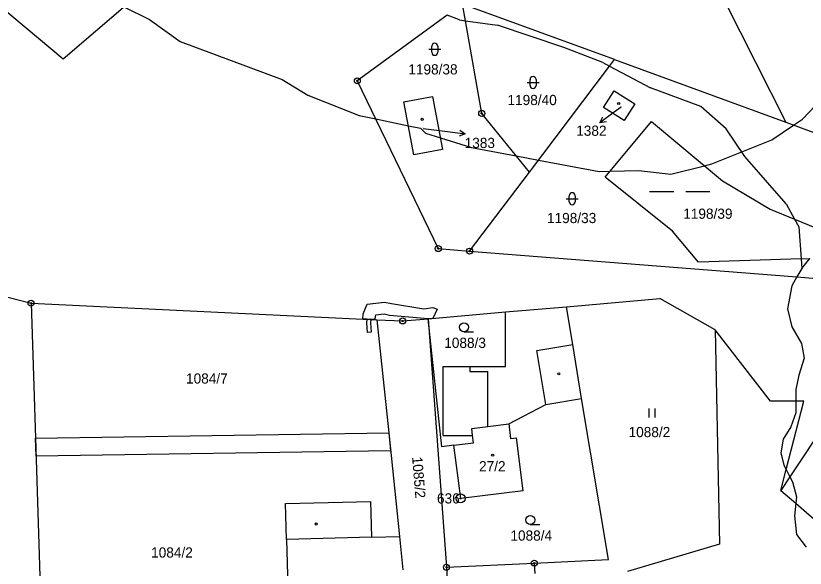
# Model space of a CAD drawing. Extents: x -439246 to -433691, y -1130252 to -1121148.
# Drawn here: x -438464.2 to -438332.6, y -1123574.8 to -1123482.7 of the extents above; entities that cross this region are included whole.
import ezdxf

# ---------------------------------------------------------------- set-up
doc = ezdxf.new("R2010")
doc.units = 0
for name, color, linetype in [('Vrstva 1', 7, 'Continuous'), ('Vrstva 16', 7, 'Continuous'), ('Vrstva 17', 7, 'Continuous'), ('Vrstva 18', 7, 'Continuous'), ('Vrstva 19', 7, 'Continuous'), ('Vrstva 24', 7, 'Continuous'), ('Vrstva 25', 7, 'Continuous'), ('Vrstva 3', 7, 'Continuous'), ('Vrstva 30', 7, 'Continuous'), ('Vrstva 37', 7, 'Continuous'), ('Vrstva 4', 7, 'Continuous'), ('Vrstva 52', 7, 'Continuous')]:
    doc.layers.add(name, color=color, linetype=linetype)

msp = doc.modelspace()

# ---------------------------------------------------------------- linework, layer by layer
at = {"layer": 'Vrstva 1'}
for p, q in [((-438389.25, -1123483.53), (-438389.74, -1123480.75)), ((-438386.53, -1123498.98), (-438389.25, -1123483.53)), ((-438364.37, -1123489.98), (-438335.85, -1123500.47)), ((-438378.59, -1123508.78), (-438365.22, -1123491.11)), ((-438378.59, -1123508.78), (-438386.53, -1123498.98)), ((-438365.96, -1123509.63), (-438358.22, -1123500.32)), ((-438358.22, -1123500.32), (-438346.4, -1123510.22)), ((-438388.55, -1123521.95), (-438378.59, -1123508.78)), ((-438354.73, -1123518.6), (-438365.96, -1123509.63)), ((-438346.4, -1123510.22), (-438338.42, -1123514.97)), ((-438338.42, -1123514.97), (-438334.38, -1123516.62)), ((-438334.38, -1123516.62), (-438328.41, -1123519.06)), ((-438350.41, -1123523.81), (-438354.73, -1123518.6)), ((-438388.55, -1123521.95), (-438333.97, -1123526.25)), ((-438333.3, -1123523.25), (-438350.41, -1123523.81)), ((-438333.3, -1123523.25), (-438331.83, -1123523.2)), ((-438461.66, -1123530.63), (-438460.93, -1123553.15)), ((-438404.01, -1123533.39), (-438402.04, -1123552.25)), ((-438460.93, -1123553.15), (-438402.04, -1123552.25)), ((-438460.93, -1123553.15), (-438459.65, -1123592.69)), ((-438402.04, -1123552.25), (-438400.24, -1123569.55)), ((-438377.77, -1123573.98), (-438377.67, -1123575.68))]:
    msp.add_line(p, q, dxfattribs=at)
for points in [[(-438456.3, -1123489.9), (-438433.99, -1123470.7)], [(-438469.05, -1123479.23), (-438456.3, -1123489.9)], [(-438364.37, -1123489.98), (-438389.74, -1123480.75)], [(-438345.94, -1123480.44), (-438335.85, -1123500.47)], [(-438392.32, -1123482.63), (-438407.27, -1123493.56)], [(-438365.22, -1123491.11), (-438364.37, -1123489.98)], [(-438407.27, -1123493.56), (-438393.78, -1123521.54)], [(-438366.22, -1123498.03), (-438364.47, -1123495.23), (-438361.03, -1123497.41), (-438362.78, -1123500.19), (-438366.22, -1123498.03)], [(-438399.5, -1123497.08), (-438394.73, -1123496.19)], [(-438394.73, -1123496.19), (-438393.05, -1123505.01)], [(-438397.84, -1123505.87), (-438399.5, -1123497.08)], [(-438335.85, -1123500.47), (-438330.11, -1123502.58)], [(-438393.05, -1123505.01), (-438397.84, -1123505.87)], [(-438393.78, -1123521.54), (-438388.55, -1123521.95)], [(-438488.42, -1123523.74), (-438461.66, -1123530.63)], [(-438333.97, -1123526.25), (-438329.34, -1123526.61)], [(-438461.66, -1123530.63), (-438404.01, -1123533.39)], [(-438372.41, -1123531.22), (-438356.83, -1123529.86)], [(-438347.62, -1123535.06), (-438356.83, -1123529.86)], [(-438395.44, -1123533.23), (-438382.54, -1123532.1)], [(-438382.54, -1123532.1), (-438372.41, -1123531.22)], [(-438382.54, -1123541.2), (-438382.54, -1123532.1)], [(-438371.36, -1123537.53), (-438372.41, -1123531.22)], [(-438316.41, -1123531.43), (-438335.17, -1123559.57)], [(-438404.01, -1123533.39), (-438399.71, -1123533.6)], [(-438399.71, -1123533.6), (-438395.44, -1123533.23)], [(-438395.44, -1123533.23), (-438392.41, -1123574.67)], [(-438393.18, -1123554.57), (-438395.44, -1123533.23)], [(-438338.37, -1123546.96), (-438347.62, -1123535.06)], [(-438347.62, -1123535.06), (-438346.87, -1123570.81)], [(-438369.87, -1123546.51), (-438371.36, -1123537.53)], [(-438392.97, -1123552.69), (-438392.97, -1123541.2)], [(-438392.97, -1123541.2), (-438388.52, -1123541.2)], [(-438388.52, -1123541.2), (-438382.54, -1123541.2)], [(-438375.85, -1123547.5), (-438369.87, -1123546.51)], [(-438365.41, -1123573.39), (-438369.87, -1123546.51)], [(-438382.02, -1123550.73), (-438375.85, -1123547.5)], [(-438334.17, -1123546.98), (-438338.37, -1123546.96)], [(-438335.79, -1123558.37), (-438332.85, -1123546.99)], [(-438332.85, -1123546.99), (-438334.17, -1123546.98)], [(-438382.02, -1123550.73), (-438381.71, -1123553.21)], [(-438392.97, -1123552.69), (-438388.05, -1123552.69)], [(-438387.9, -1123553.9), (-438388.05, -1123552.69)], [(-438381.71, -1123553.21), (-438380.72, -1123553.09)], [(-438379.62, -1123561.92), (-438380.72, -1123553.09)], [(-438391.16, -1123554.31), (-438393.18, -1123554.57)], [(-438391.16, -1123554.31), (-438387.9, -1123553.9)], [(-438390.03, -1123563.22), (-438391.16, -1123554.31)], [(-438336.68, -1123561.84), (-438335.79, -1123558.37)], [(-438335.17, -1123559.57), (-438336.68, -1123561.84)], [(-438379.62, -1123561.92), (-438390.03, -1123563.22)], [(-438336.68, -1123561.84), (-438334.18, -1123564)], [(-438419.23, -1123564.05), (-438405.01, -1123563.68)], [(-438404.85, -1123569.67), (-438405.01, -1123563.68)], [(-438419.07, -1123570.05), (-438419.23, -1123564.05)], [(-438334.18, -1123564), (-438321.87, -1123574.68)], [(-438419.07, -1123570.05), (-438418.87, -1123577.86)], [(-438404.85, -1123569.67), (-438400.24, -1123569.55)], [(-438400.24, -1123569.55), (-438399.66, -1123575.12)], [(-438346.87, -1123570.81), (-438362.22, -1123575.37)], [(-438392.41, -1123574.67), (-438377.77, -1123573.98)], [(-438377.77, -1123573.98), (-438365.41, -1123573.39)], [(-438392.41, -1123574.67), (-438391.41, -1123593.5)]]:
    msp.add_lwpolyline(points, dxfattribs=at)
at = {"layer": 'Vrstva 16'}
for p, q in [((-438364.44, -1123498.79), (-438366.85, -1123500.57)), ((-438392.24, -1123502.02), (-438389.27, -1123502.41))]:
    msp.add_line(p, q, dxfattribs=at)
for points in [[(-438363.28, -1123497.93), (-438364.44, -1123498.79)], [(-438365.75, -1123500.38), (-438366.85, -1123500.57), (-438366.35, -1123499.58)], [(-438396.32, -1123501.49), (-438392.24, -1123502.02)], [(-438390.19, -1123501.79), (-438389.27, -1123502.41), (-438390.32, -1123502.78)]]:
    msp.add_lwpolyline(points, dxfattribs=at)
at = {"layer": 'Vrstva 24'}
for centre, radius in [((-438407.27, -1123493.56), 0.5), ((-438407.27, -1123493.56), 0.1), ((-438386.53, -1123498.98), 0.5), ((-438386.53, -1123498.98), 0.1), ((-438393.78, -1123521.54), 0.5), ((-438393.78, -1123521.54), 0.1), ((-438388.55, -1123521.95), 0.5), ((-438388.55, -1123521.95), 0.1), ((-438461.66, -1123530.63), 0.5), ((-438461.66, -1123530.63), 0.1), ((-438399.71, -1123533.6), 0.5), ((-438399.71, -1123533.6), 0.1), ((-438390.06, -1123563.18), 0.75), ((-438390.06, -1123563.18), 0.1), ((-438392.41, -1123574.67), 0.5), ((-438377.77, -1123573.98), 0.5), ((-438377.77, -1123573.98), 0.1), ((-438392.41, -1123574.67), 0.1)]:
    msp.add_circle(centre, radius, dxfattribs=at)
at = {"layer": 'Vrstva 25'}
for p, q in [((-438395.36, -1123488.29), (-438393.36, -1123488.29)), ((-438394.86, -1123488.79), (-438394.86, -1123487.79)), ((-438393.86, -1123487.79), (-438393.86, -1123488.79)), ((-438378.97, -1123493.83), (-438376.97, -1123493.83)), ((-438378.47, -1123494.33), (-438378.47, -1123493.33)), ((-438377.47, -1123493.33), (-438377.47, -1123494.33)), ((-438358.54, -1123512), (-438354.52, -1123512)), ((-438352.51, -1123512), (-438348.48, -1123512)), ((-438372.46, -1123513.21), (-438370.46, -1123513.21)), ((-438371.96, -1123513.71), (-438371.96, -1123512.71)), ((-438370.96, -1123512.71), (-438370.96, -1123513.71)), ((-438389.49, -1123535.39), (-438387.89, -1123535.39)), ((-438358.6, -1123549.72), (-438358.6, -1123548.22)), ((-438357.6, -1123549.72), (-438357.6, -1123548.22)), ((-438378.45, -1123567.53), (-438376.85, -1123567.53))]:
    msp.add_line(p, q, dxfattribs=at)
for centre, radius in [((-438363.7, -1123497.33), 0.175), ((-438396.46, -1123499.97), 0.175), ((-438389.49, -1123534.64), 0.75), ((-438373.68, -1123542.4), 0.175), ((-438384.7, -1123555.97), 0.175), ((-438378.45, -1123566.78), 0.75), ((-438414.14, -1123567.46), 0.175)]:
    msp.add_circle(centre, radius, dxfattribs=at)
for centre, start, end in [((-438394.36, -1123487.79), 0, 180), ((-438394.36, -1123488.79), 180, 0), ((-438377.97, -1123493.33), 0, 180), ((-438377.97, -1123494.33), 180, 0), ((-438371.46, -1123512.71), 0, 180), ((-438371.46, -1123513.71), 180, 0)]:
    msp.add_arc(centre, 0.5, start, end, dxfattribs=at)
at = {"layer": 'Vrstva 3'}
for points in [[(-438366.22, -1123498.03), (-438364.47, -1123495.23), (-438361.03, -1123497.41), (-438362.78, -1123500.19), (-438366.22, -1123498.03)], [(-438399.5, -1123497.08), (-438394.73, -1123496.19)], [(-438394.73, -1123496.19), (-438393.05, -1123505.01)], [(-438397.84, -1123505.87), (-438399.5, -1123497.08)], [(-438393.05, -1123505.01), (-438397.84, -1123505.87)], [(-438385.49, -1123551.17), (-438382.02, -1123550.73)], [(-438382.02, -1123550.73), (-438381.71, -1123553.21)], [(-438388.2, -1123551.52), (-438385.49, -1123551.17)], [(-438388.05, -1123552.69), (-438388.2, -1123551.52)], [(-438387.9, -1123553.9), (-438388.05, -1123552.69)], [(-438381.71, -1123553.21), (-438380.72, -1123553.09)], [(-438379.62, -1123561.92), (-438380.72, -1123553.09)], [(-438391.16, -1123554.31), (-438387.9, -1123553.9)], [(-438390.03, -1123563.22), (-438391.16, -1123554.31)], [(-438379.62, -1123561.92), (-438390.03, -1123563.22)]]:
    msp.add_lwpolyline(points, dxfattribs=at)
at = {"layer": 'Vrstva 30'}
for points in [[(-438405.63, -1123533.31), (-438406.33, -1123533.28), (-438406.28, -1123532.4), (-438405.63, -1123530.81), (-438402.73, -1123530.46), (-438401.58, -1123530.71), (-438396.17, -1123531.55), (-438394.71, -1123531.34), (-438393.98, -1123531.63), (-438394.7, -1123533.16), (-438395.44, -1123533.23), (-438401.89, -1123532.68), (-438402.82, -1123532.49), (-438404.22, -1123532.65), (-438404.3, -1123532.84), (-438404.33, -1123533.37), (-438405.03, -1123533.34), (-438405.63, -1123533.31)], [(-438405.03, -1123533.34), (-438405.06, -1123533.92), (-438404.99, -1123535.47), (-438405.59, -1123535.5), (-438405.66, -1123533.89), (-438405.63, -1123533.31), (-438405.03, -1123533.34)], [(-438402.04, -1123552.25), (-438401.73, -1123555.25), (-438460.83, -1123556.14), (-438460.93, -1123553.15), (-438402.04, -1123552.25)]]:
    msp.add_lwpolyline(points, dxfattribs=at)
at = {"layer": 'Vrstva 37'}
for centre in [(-438363.7, -1123497.33), (-438396.46, -1123499.97), (-438384.7, -1123555.97)]:
    msp.add_circle(centre, 0.175, dxfattribs=at)
at = {"layer": 'Vrstva 4'}
for p, q in [((-438390.24, -1123483.39), (-438389.25, -1123483.53)), ((-438389.25, -1123483.53), (-438383.9, -1123484.28)), ((-438366.36, -1123490.5), (-438365.22, -1123491.11)), ((-438365.22, -1123491.11), (-438358.42, -1123494.73)), ((-438335.8, -1123514.04), (-438334.38, -1123516.62)), ((-438334.38, -1123516.62), (-438333.68, -1123517.9)), ((-438333.68, -1123517.9), (-438333.3, -1123523.25)), ((-438333.3, -1123523.25), (-438333.19, -1123524.85)), ((-438333.19, -1123524.85), (-438331.83, -1123523.2))]:
    msp.add_line(p, q, dxfattribs=at)
for points in [[(-438390.24, -1123483.39), (-438392.32, -1123482.63)], [(-438372.83, -1123488), (-438383.9, -1123484.28)], [(-438366.36, -1123490.5), (-438372.83, -1123488)], [(-438350.02, -1123497.82), (-438358.42, -1123494.73)], [(-438345.77, -1123501.54), (-438350.02, -1123497.82)], [(-438342.67, -1123506.15), (-438345.77, -1123501.54)], [(-438335.8, -1123514.04), (-438342.67, -1123506.15)], [(-438333.19, -1123524.85), (-438333.97, -1123526.25)], [(-438333.97, -1123526.25), (-438334.82, -1123527.76)], [(-438334.82, -1123527.76), (-438335.55, -1123531.55)], [(-438335.55, -1123531.55), (-438334.82, -1123534.56)], [(-438334.82, -1123534.56), (-438333.23, -1123537.35)], [(-438377.34, -1123538.52), (-438371.36, -1123537.53)], [(-438333.23, -1123537.35), (-438332.76, -1123539.78)], [(-438375.85, -1123547.5), (-438377.34, -1123538.52)], [(-438332.76, -1123539.78), (-438333.68, -1123542.62)], [(-438388.52, -1123541.2), (-438388.52, -1123542.03)], [(-438388.52, -1123542.03), (-438385.49, -1123542.03)], [(-438385.49, -1123551.17), (-438385.49, -1123542.03)], [(-438333.68, -1123542.62), (-438334.17, -1123545.01)], [(-438334.17, -1123545.01), (-438334.17, -1123546.98)], [(-438334.17, -1123546.98), (-438334.17, -1123548.91)], [(-438334.17, -1123548.91), (-438334.98, -1123551.27)], [(-438385.49, -1123551.17), (-438382.02, -1123550.73)], [(-438388.2, -1123551.52), (-438385.49, -1123551.17)], [(-438388.05, -1123552.69), (-438388.2, -1123551.52)], [(-438334.98, -1123551.27), (-438336.3, -1123553.32)], [(-438336.3, -1123553.32), (-438336.64, -1123555.6)], [(-438336.64, -1123555.6), (-438336.17, -1123557.62)], [(-438336.17, -1123557.62), (-438335.79, -1123558.37)], [(-438335.79, -1123558.37), (-438335.17, -1123559.57)], [(-438335.17, -1123559.57), (-438334.72, -1123560.43)], [(-438334.72, -1123560.43), (-438334.08, -1123562.91)], [(-438334.08, -1123562.91), (-438334.18, -1123564)], [(-438334.18, -1123564), (-438334.37, -1123566.09)], [(-438334.37, -1123566.09), (-438334.06, -1123569.21)], [(-438334.06, -1123569.21), (-438332.44, -1123571.32)], [(-438404.85, -1123569.67), (-438419.07, -1123570.05)]]:
    msp.add_lwpolyline(points, dxfattribs=at)
at = {"layer": 'Vrstva 52'}
msp.add_lwpolyline([(-438446.2, -1123481.21), (-438441.94, -1123483.34), (-438436.82, -1123486.97), (-438419.78, -1123493.36), (-438415.52, -1123495.92), (-438406.99, -1123499.33), (-438405.87, -1123499.56), (-438404.21, -1123499.9), (-438399.53, -1123500.88), (-438398.75, -1123501.04), (-438396.76, -1123501.46), (-438395.91, -1123502.31), (-438393.42, -1123503.07), (-438388.24, -1123504.65), (-438380.79, -1123506.06), (-438377.07, -1123506.77), (-438366.93, -1123508.7), (-438365.14, -1123508.64), (-438360.33, -1123508.49), (-438355, -1123509.13), (-438349.38, -1123507.72), (-438348.18, -1123507.42), (-438338.17, -1123503.37), (-438334.54, -1123500.95), (-438333.06, -1123499.96), (-438324.32, -1123490.8)], dxfattribs=at)

# ---------------------------------------------------------------- texts
at = {"layer": 'Vrstva 16'}
for s, p in [('1382', (-438370.78, -1123502.72)), ('1383', (-438389.38, -1123504.76))]:
    msp.add_text(s, height=1.7, dxfattribs=at).set_placement(p)
at = {"layer": 'Vrstva 17'}
msp.add_text('636', height=1.7, dxfattribs=at).set_placement((-438393.99, -1123564.03))
at = {"layer": 'Vrstva 18'}
for s, p in [('1198/38', (-438398.77, -1123492.49)), ('1198/40', (-438382.24, -1123497.6)), ('1198/39', (-438352.94, -1123516.56)), ('1198/33', (-438375.65, -1123517.28)), ('1088/3', (-438392.78, -1123538.09)), ('1084/7', (-438435.83, -1123544.04)), ('1088/2', (-438362.05, -1123552.97)), ('1088/4', (-438381.75, -1123570.23)), ('1084/2', (-438441.65, -1123573.05))]:
    msp.add_text(s, height=1.7, dxfattribs=at).set_placement(p)
msp.add_text('1085/2', height=1.7, rotation=274.7309, dxfattribs=at).set_placement((-438398.15, -1123556.29))
at = {"layer": 'Vrstva 19'}
for s, height, p in [('1382', 0.1, (-438363.41, -1123497.93)), ('1383', 0.1, (-438396.46, -1123501.49)), ('27/2', 1.7, (-438386.98, -1123558.67))]:
    msp.add_text(s, height=height, dxfattribs=at).set_placement(p)

doc.saveas('drawing.dxf')
